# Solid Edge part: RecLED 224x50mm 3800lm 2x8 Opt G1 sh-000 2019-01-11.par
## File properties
Author: lukasz.lemanski
Template: iso metric part.par
Last saved by: lukasz.lemanski
Revision: 1
Application: Solid Edge
Username: lukasz.lemanski
Gęstość: 0,000 kg/m^3
Dokładność: 0,990
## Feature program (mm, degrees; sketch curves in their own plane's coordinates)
body "unnamed Body 1"
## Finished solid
Body 1: solid body, 1037 faces, 2679 edges, 1661 vertices.
  Faces by surface: plane 469, cylinder 402, spline 80, torus 43, cone 26, sphere 10, spun 7
  Edges by curve: line 1596, circle 627, curve on surface 282, ellipse 130, spline 38, intersection 6
Bounding box of the edges (mm; curved faces can reach further): 49.500 x 4.950 x 223.000, from (-24.75, -3.45, -111.5) to (24.75, 1.5, 111.5).
Cylindrical faces by radius (mm): R0.05 x64, R0.1 x192, R0.2 x55, R0.2002 x2, R0.2169 x3, R0.25 x12, R0.3 x2, R0.3373 x3, R0.4 x8, R0.4006 x2, R0.4008 x2, R0.525 x2, R0.6 x12, R1 x7, R1.05 x16, R1.0894 x2, R1.1 x14, R1.6 x4
Conical faces (half-angle, radius in mm at the cone's reference point): 0.5 deg R0.5056 x4, 0.5 deg R1.0082 x4, 1 deg R0.5511 x2, 10 deg R0.2132 x2, 10 deg R0.4132 x2, 18.4844 deg R1.0657 x4, 27.363 deg R0.6214 x2, 45 deg R0.575 x2, 45 deg R0.625 x4
Toroidal faces (ring radius, tube radius in mm): R-0.0731 r1.395 x16, R0.1 r0.2 x1, R0.8 r0.2 x4, R0.8522 r0.3 x2, R0.9002 r0.2 x1, R0.9018 r0.2 x1, R1.3 r0.2 x2, R1.4708 r0.15 x16
Spherical faces by radius (mm): R0.2 x8, R0.6 x2
Planar faces by outward normal: +x 77, +y 24, +z 73, -x 77, -y 36, -z 98, oblique 84
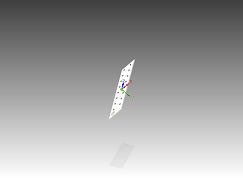
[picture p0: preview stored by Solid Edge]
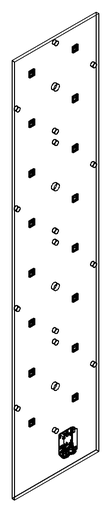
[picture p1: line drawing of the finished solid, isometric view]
